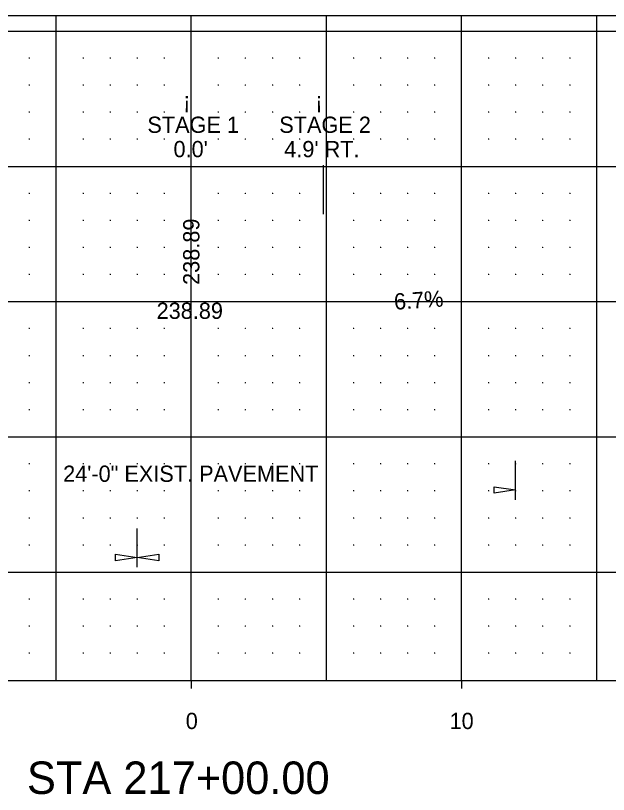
# Model space of a CAD drawing. Extents: x -80 to 80, y 222 to 253.
# Drawn here: x -6.5 to 15.43, y 221.78 to 250.57 of the extents above; entities that cross this region are included whole.
import ezdxf

# ---------------------------------------------------------------- set-up
doc = ezdxf.new("R2010")
doc.units = 0
for name, color, linetype in [('Default', 7, 'Continuous'), ('DSN_DRFT_XS Border Grid', 7, 'Continuous'), ('DSN_DRFT_XS Grid Annotations', 7, 'Continuous'), ('DSN_DRFT_XS Grid Major', 7, 'Continuous'), ('DSN_DRFT_XS Grid Minor', 7, 'Continuous'), ('DSN_DRFT_XS MOT CL Annotations', 7, 'Continuous'), ('DSN_DRFT_XS MOT STG Annotations', 7, 'Continuous'), ('DSN_RDWY_XS Annotation', 7, 'Continuous')]:
    doc.layers.add(name, color=color, linetype=linetype)

msp = doc.modelspace()

# ---------------------------------------------------------------- linework, layer by layer
at = {"layer": 'DSN_DRFT_XS Border Grid'}
for p, q in [((-77.5, 250.573), (77.5, 250.573)), ((-77.5, 226), (77.5, 226))]:
    msp.add_line(p, q, dxfattribs=at)
at = {"layer": 'DSN_DRFT_XS Grid Major'}
for p, q in [((-5, 226), (-5, 250.573)), ((0, 226), (0, 250.573)), ((5, 226), (5, 250.573)), ((10, 226), (10, 250.573)), ((15, 226), (15, 250.573)), ((-77.5, 250), (77.5, 250)), ((-77.5, 245), (77.5, 245)), ((-77.5, 240), (77.5, 240)), ((-77.5, 235), (77.5, 235)), ((-77.5, 230), (77.5, 230)), ((0, 226), (0, 225.7)), ((10, 226), (10, 225.7))]:
    msp.add_line(p, q, dxfattribs=at)
at = {"layer": 'DSN_DRFT_XS Grid Minor'}
for p, q in [((-5.988, 249), (-6.012, 249)), ((-6, 249.012), (-6, 248.988)), ((-3.988, 249), (-4.012, 249)), ((-4, 249.012), (-4, 248.988)), ((-2.988, 249), (-3.012, 249)), ((-3, 249.012), (-3, 248.988)), ((-1.988, 249), (-2.012, 249)), ((-2, 249.012), (-2, 248.988)), ((-0.988, 249), (-1.012, 249)), ((-1, 249.012), (-1, 248.988)), ((1.012, 249), (0.988, 249)), ((1, 249.012), (1, 248.988)), ((2.012, 249), (1.988, 249)), ((2, 249.012), (2, 248.988)), ((3.012, 249), (2.988, 249)), ((3, 249.012), (3, 248.988)), ((4.012, 249), (3.988, 249)), ((4, 249.012), (4, 248.988)), ((6.012, 249), (5.988, 249)), ((6, 249.012), (6, 248.988)), ((7.012, 249), (6.988, 249)), ((7, 249.012), (7, 248.988)), ((8.012, 249), (7.988, 249)), ((8, 249.012), (8, 248.988)), ((9.012, 249), (8.988, 249)), ((9, 249.012), (9, 248.988)), ((11.012, 249), (10.988, 249)), ((11, 249.012), (11, 248.988)), ((12.012, 249), (11.988, 249)), ((12, 249.012), (12, 248.988)), ((13.012, 249), (12.988, 249)), ((13, 249.012), (13, 248.988)), ((14.012, 249), (13.988, 249)), ((14, 249.012), (14, 248.988)), ((-5.988, 248), (-6.012, 248)), ((-6, 248.012), (-6, 247.988)), ((-3.988, 248), (-4.012, 248)), ((-4, 248.012), (-4, 247.988)), ((-2.988, 248), (-3.012, 248)), ((-3, 248.012), (-3, 247.988)), ((-1.988, 248), (-2.012, 248)), ((-2, 248.012), (-2, 247.988)), ((-0.988, 248), (-1.012, 248)), ((-1, 248.012), (-1, 247.988)), ((1.012, 248), (0.988, 248)), ((1, 248.012), (1, 247.988)), ((2.012, 248), (1.988, 248)), ((2, 248.012), (2, 247.988)), ((3.012, 248), (2.988, 248)), ((3, 248.012), (3, 247.988)), ((4.012, 248), (3.988, 248)), ((4, 248.012), (4, 247.988)), ((6.012, 248), (5.988, 248)), ((6, 248.012), (6, 247.988)), ((7.012, 248), (6.988, 248)), ((7, 248.012), (7, 247.988)), ((8.012, 248), (7.988, 248)), ((8, 248.012), (8, 247.988)), ((9.012, 248), (8.988, 248)), ((9, 248.012), (9, 247.988)), ((11.012, 248), (10.988, 248)), ((11, 248.012), (11, 247.988)), ((12.012, 248), (11.988, 248)), ((12, 248.012), (12, 247.988)), ((13.012, 248), (12.988, 248)), ((13, 248.012), (13, 247.988)), ((14.012, 248), (13.988, 248)), ((14, 248.012), (14, 247.988)), ((-5.988, 247), (-6.012, 247)), ((-6, 247.012), (-6, 246.988)), ((-3.988, 247), (-4.012, 247)), ((-4, 247.012), (-4, 246.988)), ((-2.988, 247), (-3.012, 247)), ((-3, 247.012), (-3, 246.988)), ((-1.988, 247), (-2.012, 247)), ((-2, 247.012), (-2, 246.988)), ((-0.988, 247), (-1.012, 247)), ((-1, 247.012), (-1, 246.988)), ((1.012, 247), (0.988, 247)), ((1, 247.012), (1, 246.988)), ((2.012, 247), (1.988, 247)), ((2, 247.012), (2, 246.988)), ((3.012, 247), (2.988, 247)), ((3, 247.012), (3, 246.988)), ((4.012, 247), (3.988, 247)), ((4, 247.012), (4, 246.988)), ((6.012, 247), (5.988, 247)), ((6, 247.012), (6, 246.988)), ((7.012, 247), (6.988, 247)), ((7, 247.012), (7, 246.988)), ((8.012, 247), (7.988, 247)), ((8, 247.012), (8, 246.988)), ((9.012, 247), (8.988, 247)), ((9, 247.012), (9, 246.988)), ((11.012, 247), (10.988, 247)), ((11, 247.012), (11, 246.988)), ((12.012, 247), (11.988, 247)), ((12, 247.012), (12, 246.988)), ((13.012, 247), (12.988, 247)), ((13, 247.012), (13, 246.988)), ((14.012, 247), (13.988, 247)), ((14, 247.012), (14, 246.988)), ((-5.988, 246), (-6.012, 246)), ((-6, 246.012), (-6, 245.988)), ((-3.988, 246), (-4.012, 246)), ((-4, 246.012), (-4, 245.988)), ((-2.988, 246), (-3.012, 246)), ((-3, 246.012), (-3, 245.988)), ((-1.988, 246), (-2.012, 246)), ((-2, 246.012), (-2, 245.988)), ((-0.988, 246), (-1.012, 246)), ((-1, 246.012), (-1, 245.988)), ((1.012, 246), (0.988, 246)), ((1, 246.012), (1, 245.988)), ((2.012, 246), (1.988, 246)), ((2, 246.012), (2, 245.988)), ((3.012, 246), (2.988, 246)), ((3, 246.012), (3, 245.988)), ((4.012, 246), (3.988, 246)), ((4, 246.012), (4, 245.988)), ((6.012, 246), (5.988, 246)), ((6, 246.012), (6, 245.988)), ((7.012, 246), (6.988, 246)), ((7, 246.012), (7, 245.988)), ((8.012, 246), (7.988, 246)), ((8, 246.012), (8, 245.988)), ((9.012, 246), (8.988, 246)), ((9, 246.012), (9, 245.988)), ((11.012, 246), (10.988, 246)), ((11, 246.012), (11, 245.988)), ((12.012, 246), (11.988, 246)), ((12, 246.012), (12, 245.988)), ((13.012, 246), (12.988, 246)), ((13, 246.012), (13, 245.988)), ((14.012, 246), (13.988, 246)), ((14, 246.012), (14, 245.988)), ((-5.988, 244), (-6.012, 244)), ((-6, 244.012), (-6, 243.988)), ((-3.988, 244), (-4.012, 244)), ((-4, 244.012), (-4, 243.988)), ((-2.988, 244), (-3.012, 244)), ((-3, 244.012), (-3, 243.988)), ((-1.988, 244), (-2.012, 244)), ((-2, 244.012), (-2, 243.988)), ((-0.988, 244), (-1.012, 244)), ((-1, 244.012), (-1, 243.988)), ((1.012, 244), (0.988, 244)), ((1, 244.012), (1, 243.988)), ((2.012, 244), (1.988, 244)), ((2, 244.012), (2, 243.988)), ((3.012, 244), (2.988, 244)), ((3, 244.012), (3, 243.988)), ((4.012, 244), (3.988, 244)), ((4, 244.012), (4, 243.988)), ((6.012, 244), (5.988, 244)), ((6, 244.012), (6, 243.988)), ((7.012, 244), (6.988, 244)), ((7, 244.012), (7, 243.988)), ((8.012, 244), (7.988, 244)), ((8, 244.012), (8, 243.988)), ((9.012, 244), (8.988, 244)), ((9, 244.012), (9, 243.988)), ((11.012, 244), (10.988, 244)), ((11, 244.012), (11, 243.988)), ((12.012, 244), (11.988, 244)), ((12, 244.012), (12, 243.988)), ((13.012, 244), (12.988, 244)), ((13, 244.012), (13, 243.988)), ((14.012, 244), (13.988, 244)), ((14, 244.012), (14, 243.988)), ((-5.988, 243), (-6.012, 243)), ((-6, 243.012), (-6, 242.988)), ((-3.988, 243), (-4.012, 243)), ((-4, 243.012), (-4, 242.988)), ((-2.988, 243), (-3.012, 243)), ((-3, 243.012), (-3, 242.988)), ((-1.988, 243), (-2.012, 243)), ((-2, 243.012), (-2, 242.988)), ((-0.988, 243), (-1.012, 243)), ((-1, 243.012), (-1, 242.988)), ((1.012, 243), (0.988, 243)), ((1, 243.012), (1, 242.988)), ((2.012, 243), (1.988, 243)), ((2, 243.012), (2, 242.988)), ((3.012, 243), (2.988, 243)), ((3, 243.012), (3, 242.988)), ((4.012, 243), (3.988, 243)), ((4, 243.012), (4, 242.988)), ((6.012, 243), (5.988, 243)), ((6, 243.012), (6, 242.988)), ((7.012, 243), (6.988, 243)), ((7, 243.012), (7, 242.988)), ((8.012, 243), (7.988, 243)), ((8, 243.012), (8, 242.988)), ((9.012, 243), (8.988, 243)), ((9, 243.012), (9, 242.988)), ((11.012, 243), (10.988, 243)), ((11, 243.012), (11, 242.988)), ((12.012, 243), (11.988, 243)), ((12, 243.012), (12, 242.988)), ((13.012, 243), (12.988, 243)), ((13, 243.012), (13, 242.988)), ((14.012, 243), (13.988, 243)), ((14, 243.012), (14, 242.988)), ((-5.988, 242), (-6.012, 242)), ((-6, 242.012), (-6, 241.988)), ((-3.988, 242), (-4.012, 242)), ((-4, 242.012), (-4, 241.988)), ((-2.988, 242), (-3.012, 242)), ((-3, 242.012), (-3, 241.988)), ((-1.988, 242), (-2.012, 242)), ((-2, 242.012), (-2, 241.988)), ((-0.988, 242), (-1.012, 242)), ((-1, 242.012), (-1, 241.988)), ((1.012, 242), (0.988, 242)), ((1, 242.012), (1, 241.988)), ((2.012, 242), (1.988, 242)), ((2, 242.012), (2, 241.988)), ((3.012, 242), (2.988, 242)), ((3, 242.012), (3, 241.988)), ((4.012, 242), (3.988, 242)), ((4, 242.012), (4, 241.988)), ((6.012, 242), (5.988, 242)), ((6, 242.012), (6, 241.988)), ((7.012, 242), (6.988, 242)), ((7, 242.012), (7, 241.988)), ((8.012, 242), (7.988, 242)), ((8, 242.012), (8, 241.988)), ((9.012, 242), (8.988, 242)), ((9, 242.012), (9, 241.988)), ((11.012, 242), (10.988, 242)), ((11, 242.012), (11, 241.988)), ((12.012, 242), (11.988, 242)), ((12, 242.012), (12, 241.988)), ((13.012, 242), (12.988, 242)), ((13, 242.012), (13, 241.988)), ((14.012, 242), (13.988, 242)), ((14, 242.012), (14, 241.988)), ((-5.988, 241), (-6.012, 241)), ((-6, 241.012), (-6, 240.988)), ((-3.988, 241), (-4.012, 241)), ((-4, 241.012), (-4, 240.988)), ((-2.988, 241), (-3.012, 241)), ((-3, 241.012), (-3, 240.988)), ((-1.988, 241), (-2.012, 241)), ((-2, 241.012), (-2, 240.988)), ((-0.988, 241), (-1.012, 241)), ((-1, 241.012), (-1, 240.988)), ((1.012, 241), (0.988, 241)), ((1, 241.012), (1, 240.988)), ((2.012, 241), (1.988, 241)), ((2, 241.012), (2, 240.988)), ((3.012, 241), (2.988, 241)), ((3, 241.012), (3, 240.988)), ((4.012, 241), (3.988, 241)), ((4, 241.012), (4, 240.988)), ((6.012, 241), (5.988, 241)), ((6, 241.012), (6, 240.988)), ((7.012, 241), (6.988, 241)), ((7, 241.012), (7, 240.988)), ((8.012, 241), (7.988, 241)), ((8, 241.012), (8, 240.988)), ((9.012, 241), (8.988, 241)), ((9, 241.012), (9, 240.988)), ((11.012, 241), (10.988, 241)), ((11, 241.012), (11, 240.988)), ((12.012, 241), (11.988, 241)), ((12, 241.012), (12, 240.988)), ((13.012, 241), (12.988, 241)), ((13, 241.012), (13, 240.988)), ((14.012, 241), (13.988, 241)), ((14, 241.012), (14, 240.988)), ((-5.988, 239), (-6.012, 239)), ((-6, 239.012), (-6, 238.988)), ((-3.988, 239), (-4.012, 239)), ((-4, 239.012), (-4, 238.988)), ((-2.988, 239), (-3.012, 239)), ((-3, 239.012), (-3, 238.988)), ((-1.988, 239), (-2.012, 239)), ((-2, 239.012), (-2, 238.988)), ((-0.988, 239), (-1.012, 239)), ((-1, 239.012), (-1, 238.988)), ((1.012, 239), (0.988, 239)), ((1, 239.012), (1, 238.988)), ((2.012, 239), (1.988, 239)), ((2, 239.012), (2, 238.988)), ((3.012, 239), (2.988, 239)), ((3, 239.012), (3, 238.988)), ((4.012, 239), (3.988, 239)), ((4, 239.012), (4, 238.988)), ((6.012, 239), (5.988, 239)), ((6, 239.012), (6, 238.988)), ((7.012, 239), (6.988, 239)), ((7, 239.012), (7, 238.988)), ((8.012, 239), (7.988, 239)), ((8, 239.012), (8, 238.988)), ((9.012, 239), (8.988, 239)), ((9, 239.012), (9, 238.988)), ((11.012, 239), (10.988, 239)), ((11, 239.012), (11, 238.988)), ((12.012, 239), (11.988, 239)), ((12, 239.012), (12, 238.988)), ((13.012, 239), (12.988, 239)), ((13, 239.012), (13, 238.988)), ((14.012, 239), (13.988, 239)), ((14, 239.012), (14, 238.988)), ((-5.988, 238), (-6.012, 238)), ((-6, 238.012), (-6, 237.988)), ((-3.988, 238), (-4.012, 238)), ((-4, 238.012), (-4, 237.988)), ((-2.988, 238), (-3.012, 238)), ((-3, 238.012), (-3, 237.988)), ((-1.988, 238), (-2.012, 238)), ((-2, 238.012), (-2, 237.988)), ((-0.988, 238), (-1.012, 238)), ((-1, 238.012), (-1, 237.988)), ((1.012, 238), (0.988, 238)), ((1, 238.012), (1, 237.988)), ((2.012, 238), (1.988, 238)), ((2, 238.012), (2, 237.988)), ((3.012, 238), (2.988, 238)), ((3, 238.012), (3, 237.988)), ((4.012, 238), (3.988, 238)), ((4, 238.012), (4, 237.988)), ((6.012, 238), (5.988, 238)), ((6, 238.012), (6, 237.988)), ((7.012, 238), (6.988, 238)), ((7, 238.012), (7, 237.988)), ((8.012, 238), (7.988, 238)), ((8, 238.012), (8, 237.988)), ((9.012, 238), (8.988, 238)), ((9, 238.012), (9, 237.988)), ((11.012, 238), (10.988, 238)), ((11, 238.012), (11, 237.988)), ((12.012, 238), (11.988, 238)), ((12, 238.012), (12, 237.988)), ((13.012, 238), (12.988, 238)), ((13, 238.012), (13, 237.988)), ((14.012, 238), (13.988, 238)), ((14, 238.012), (14, 237.988)), ((-5.988, 237), (-6.012, 237)), ((-6, 237.012), (-6, 236.988)), ((-3.988, 237), (-4.012, 237)), ((-4, 237.012), (-4, 236.988)), ((-2.988, 237), (-3.012, 237)), ((-3, 237.012), (-3, 236.988)), ((-1.988, 237), (-2.012, 237)), ((-2, 237.012), (-2, 236.988)), ((-0.988, 237), (-1.012, 237)), ((-1, 237.012), (-1, 236.988)), ((1.012, 237), (0.988, 237)), ((1, 237.012), (1, 236.988)), ((2.012, 237), (1.988, 237)), ((2, 237.012), (2, 236.988)), ((3.012, 237), (2.988, 237)), ((3, 237.012), (3, 236.988)), ((4.012, 237), (3.988, 237)), ((4, 237.012), (4, 236.988)), ((6.012, 237), (5.988, 237)), ((6, 237.012), (6, 236.988)), ((7.012, 237), (6.988, 237)), ((7, 237.012), (7, 236.988)), ((8.012, 237), (7.988, 237)), ((8, 237.012), (8, 236.988)), ((9.012, 237), (8.988, 237)), ((9, 237.012), (9, 236.988)), ((11.012, 237), (10.988, 237)), ((11, 237.012), (11, 236.988)), ((12.012, 237), (11.988, 237)), ((12, 237.012), (12, 236.988)), ((13.012, 237), (12.988, 237)), ((13, 237.012), (13, 236.988)), ((14.012, 237), (13.988, 237)), ((14, 237.012), (14, 236.988)), ((-5.988, 236), (-6.012, 236)), ((-6, 236.012), (-6, 235.988)), ((-3.988, 236), (-4.012, 236)), ((-4, 236.012), (-4, 235.988)), ((-2.988, 236), (-3.012, 236)), ((-3, 236.012), (-3, 235.988)), ((-1.988, 236), (-2.012, 236)), ((-2, 236.012), (-2, 235.988)), ((-0.988, 236), (-1.012, 236)), ((-1, 236.012), (-1, 235.988)), ((1.012, 236), (0.988, 236)), ((1, 236.012), (1, 235.988)), ((2.012, 236), (1.988, 236)), ((2, 236.012), (2, 235.988)), ((3.012, 236), (2.988, 236)), ((3, 236.012), (3, 235.988)), ((4.012, 236), (3.988, 236)), ((4, 236.012), (4, 235.988)), ((6.012, 236), (5.988, 236)), ((6, 236.012), (6, 235.988)), ((7.012, 236), (6.988, 236)), ((7, 236.012), (7, 235.988)), ((8.012, 236), (7.988, 236)), ((8, 236.012), (8, 235.988)), ((9.012, 236), (8.988, 236)), ((9, 236.012), (9, 235.988)), ((11.012, 236), (10.988, 236)), ((11, 236.012), (11, 235.988)), ((12.012, 236), (11.988, 236)), ((12, 236.012), (12, 235.988)), ((13.012, 236), (12.988, 236)), ((13, 236.012), (13, 235.988)), ((14.012, 236), (13.988, 236)), ((14, 236.012), (14, 235.988)), ((-5.988, 234), (-6.012, 234)), ((-6, 234.012), (-6, 233.988)), ((-3.988, 234), (-4.012, 234)), ((-4, 234.012), (-4, 233.988)), ((-2.988, 234), (-3.012, 234)), ((-3, 234.012), (-3, 233.988)), ((-1.988, 234), (-2.012, 234)), ((-2, 234.012), (-2, 233.988)), ((-0.988, 234), (-1.012, 234)), ((-1, 234.012), (-1, 233.988)), ((1.012, 234), (0.988, 234)), ((1, 234.012), (1, 233.988)), ((2.012, 234), (1.988, 234)), ((2, 234.012), (2, 233.988)), ((3.012, 234), (2.988, 234)), ((3, 234.012), (3, 233.988)), ((4.012, 234), (3.988, 234)), ((4, 234.012), (4, 233.988)), ((6.012, 234), (5.988, 234)), ((6, 234.012), (6, 233.988)), ((7.012, 234), (6.988, 234)), ((7, 234.012), (7, 233.988)), ((8.012, 234), (7.988, 234)), ((8, 234.012), (8, 233.988)), ((9.012, 234), (8.988, 234)), ((9, 234.012), (9, 233.988)), ((11.012, 234), (10.988, 234)), ((11, 234.012), (11, 233.988)), ((12.012, 234), (11.988, 234)), ((12, 234.012), (12, 233.988)), ((13.012, 234), (12.988, 234)), ((13, 234.012), (13, 233.988)), ((14.012, 234), (13.988, 234)), ((14, 234.012), (14, 233.988)), ((-5.988, 233), (-6.012, 233)), ((-6, 233.012), (-6, 232.988)), ((-3.988, 233), (-4.012, 233)), ((-4, 233.012), (-4, 232.988)), ((-2.988, 233), (-3.012, 233)), ((-3, 233.012), (-3, 232.988)), ((-1.988, 233), (-2.012, 233)), ((-2, 233.012), (-2, 232.988)), ((-0.988, 233), (-1.012, 233)), ((-1, 233.012), (-1, 232.988)), ((1.012, 233), (0.988, 233)), ((1, 233.012), (1, 232.988)), ((2.012, 233), (1.988, 233)), ((2, 233.012), (2, 232.988)), ((3.012, 233), (2.988, 233)), ((3, 233.012), (3, 232.988)), ((4.012, 233), (3.988, 233)), ((4, 233.012), (4, 232.988)), ((6.012, 233), (5.988, 233)), ((6, 233.012), (6, 232.988)), ((7.012, 233), (6.988, 233)), ((7, 233.012), (7, 232.988)), ((8.012, 233), (7.988, 233)), ((8, 233.012), (8, 232.988)), ((9.012, 233), (8.988, 233)), ((9, 233.012), (9, 232.988)), ((11.012, 233), (10.988, 233)), ((11, 233.012), (11, 232.988)), ((12.012, 233), (11.988, 233)), ((12, 233.012), (12, 232.988)), ((13.012, 233), (12.988, 233)), ((13, 233.012), (13, 232.988)), ((14.012, 233), (13.988, 233)), ((14, 233.012), (14, 232.988)), ((-5.988, 232), (-6.012, 232)), ((-6, 232.012), (-6, 231.988)), ((-3.988, 232), (-4.012, 232)), ((-4, 232.012), (-4, 231.988)), ((-2.988, 232), (-3.012, 232)), ((-3, 232.012), (-3, 231.988)), ((-1.988, 232), (-2.012, 232)), ((-2, 232.012), (-2, 231.988)), ((-0.988, 232), (-1.012, 232)), ((-1, 232.012), (-1, 231.988)), ((1.012, 232), (0.988, 232)), ((1, 232.012), (1, 231.988)), ((2.012, 232), (1.988, 232)), ((2, 232.012), (2, 231.988)), ((3.012, 232), (2.988, 232)), ((3, 232.012), (3, 231.988)), ((4.012, 232), (3.988, 232)), ((4, 232.012), (4, 231.988)), ((6.012, 232), (5.988, 232)), ((6, 232.012), (6, 231.988)), ((7.012, 232), (6.988, 232)), ((7, 232.012), (7, 231.988)), ((8.012, 232), (7.988, 232)), ((8, 232.012), (8, 231.988)), ((9.012, 232), (8.988, 232)), ((9, 232.012), (9, 231.988)), ((11.012, 232), (10.988, 232)), ((11, 232.012), (11, 231.988)), ((12.012, 232), (11.988, 232)), ((12, 232.012), (12, 231.988)), ((13.012, 232), (12.988, 232)), ((13, 232.012), (13, 231.988)), ((14.012, 232), (13.988, 232)), ((14, 232.012), (14, 231.988)), ((-5.988, 231), (-6.012, 231)), ((-6, 231.012), (-6, 230.988)), ((-3.988, 231), (-4.012, 231)), ((-4, 231.012), (-4, 230.988)), ((-2.988, 231), (-3.012, 231)), ((-3, 231.012), (-3, 230.988)), ((-1.988, 231), (-2.012, 231)), ((-2, 231.012), (-2, 230.988)), ((-0.988, 231), (-1.012, 231)), ((-1, 231.012), (-1, 230.988)), ((1.012, 231), (0.988, 231)), ((1, 231.012), (1, 230.988)), ((2.012, 231), (1.988, 231)), ((2, 231.012), (2, 230.988)), ((3.012, 231), (2.988, 231)), ((3, 231.012), (3, 230.988)), ((4.012, 231), (3.988, 231)), ((4, 231.012), (4, 230.988)), ((6.012, 231), (5.988, 231)), ((6, 231.012), (6, 230.988)), ((7.012, 231), (6.988, 231)), ((7, 231.012), (7, 230.988)), ((8.012, 231), (7.988, 231)), ((8, 231.012), (8, 230.988)), ((9.012, 231), (8.988, 231)), ((9, 231.012), (9, 230.988)), ((11.012, 231), (10.988, 231)), ((11, 231.012), (11, 230.988)), ((12.012, 231), (11.988, 231)), ((12, 231.012), (12, 230.988)), ((13.012, 231), (12.988, 231)), ((13, 231.012), (13, 230.988)), ((14.012, 231), (13.988, 231)), ((14, 231.012), (14, 230.988)), ((-5.988, 229), (-6.012, 229)), ((-6, 229.012), (-6, 228.988)), ((-3.988, 229), (-4.012, 229)), ((-4, 229.012), (-4, 228.988)), ((-2.988, 229), (-3.012, 229)), ((-3, 229.012), (-3, 228.988)), ((-1.988, 229), (-2.012, 229)), ((-2, 229.012), (-2, 228.988)), ((-0.988, 229), (-1.012, 229)), ((-1, 229.012), (-1, 228.988)), ((1.012, 229), (0.988, 229)), ((1, 229.012), (1, 228.988)), ((2.012, 229), (1.988, 229)), ((2, 229.012), (2, 228.988)), ((3.012, 229), (2.988, 229)), ((3, 229.012), (3, 228.988)), ((4.012, 229), (3.988, 229)), ((4, 229.012), (4, 228.988)), ((6.012, 229), (5.988, 229)), ((6, 229.012), (6, 228.988)), ((7.012, 229), (6.988, 229)), ((7, 229.012), (7, 228.988)), ((8.012, 229), (7.988, 229)), ((8, 229.012), (8, 228.988)), ((9.012, 229), (8.988, 229)), ((9, 229.012), (9, 228.988)), ((11.012, 229), (10.988, 229)), ((11, 229.012), (11, 228.988)), ((12.012, 229), (11.988, 229)), ((12, 229.012), (12, 228.988)), ((13.012, 229), (12.988, 229)), ((13, 229.012), (13, 228.988)), ((14.012, 229), (13.988, 229)), ((14, 229.012), (14, 228.988)), ((-5.988, 228), (-6.012, 228)), ((-6, 228.012), (-6, 227.988)), ((-3.988, 228), (-4.012, 228)), ((-4, 228.012), (-4, 227.988)), ((-2.988, 228), (-3.012, 228)), ((-3, 228.012), (-3, 227.988)), ((-1.988, 228), (-2.012, 228)), ((-2, 228.012), (-2, 227.988)), ((-0.988, 228), (-1.012, 228)), ((-1, 228.012), (-1, 227.988)), ((1.012, 228), (0.988, 228)), ((1, 228.012), (1, 227.988)), ((2.012, 228), (1.988, 228)), ((2, 228.012), (2, 227.988)), ((3.012, 228), (2.988, 228)), ((3, 228.012), (3, 227.988)), ((4.012, 228), (3.988, 228)), ((4, 228.012), (4, 227.988)), ((6.012, 228), (5.988, 228)), ((6, 228.012), (6, 227.988)), ((7.012, 228), (6.988, 228)), ((7, 228.012), (7, 227.988)), ((8.012, 228), (7.988, 228)), ((8, 228.012), (8, 227.988)), ((9.012, 228), (8.988, 228)), ((9, 228.012), (9, 227.988)), ((11.012, 228), (10.988, 228)), ((11, 228.012), (11, 227.988)), ((12.012, 228), (11.988, 228)), ((12, 228.012), (12, 227.988)), ((13.012, 228), (12.988, 228)), ((13, 228.012), (13, 227.988)), ((14.012, 228), (13.988, 228)), ((14, 228.012), (14, 227.988)), ((-5.988, 227), (-6.012, 227)), ((-6, 227.012), (-6, 226.988)), ((-3.988, 227), (-4.012, 227)), ((-4, 227.012), (-4, 226.988)), ((-2.988, 227), (-3.012, 227)), ((-3, 227.012), (-3, 226.988)), ((-1.988, 227), (-2.012, 227)), ((-2, 227.012), (-2, 226.988)), ((-0.988, 227), (-1.012, 227)), ((-1, 227.012), (-1, 226.988)), ((1.012, 227), (0.988, 227)), ((1, 227.012), (1, 226.988)), ((2.012, 227), (1.988, 227)), ((2, 227.012), (2, 226.988)), ((3.012, 227), (2.988, 227)), ((3, 227.012), (3, 226.988)), ((4.012, 227), (3.988, 227)), ((4, 227.012), (4, 226.988)), ((6.012, 227), (5.988, 227)), ((6, 227.012), (6, 226.988)), ((7.012, 227), (6.988, 227)), ((7, 227.012), (7, 226.988)), ((8.012, 227), (7.988, 227)), ((8, 227.012), (8, 226.988)), ((9.012, 227), (8.988, 227)), ((9, 227.012), (9, 226.988)), ((11.012, 227), (10.988, 227)), ((11, 227.012), (11, 226.988)), ((12.012, 227), (11.988, 227)), ((12, 227.012), (12, 226.988)), ((13.012, 227), (12.988, 227)), ((13, 227.012), (13, 226.988)), ((14.012, 227), (13.988, 227)), ((14, 227.012), (14, 226.988))]:
    msp.add_line(p, q, dxfattribs=at)
at = {"layer": 'DSN_DRFT_XS MOT CL Annotations'}
for p, q in [((0, 243.238), (0, 245.038)), ((4.889, 243.238), (4.889, 245.038))]:
    msp.add_line(p, q, dxfattribs=at)
at = {"layer": 'DSN_DRFT_XS MOT STG Annotations'}
for p, q in [((12, 232.678), (12, 234.118)), ((-2, 230.178), (-2, 231.618)), ((-2, 230.178), (-2, 231.618))]:
    msp.add_line(p, q, dxfattribs=at)
for points in [[(11.2, 233.158), (12, 233.038), (11.2, 232.918)], [(-2.8, 230.658), (-2, 230.538), (-2.8, 230.418)], [(-1.2, 230.418), (-2, 230.538), (-1.2, 230.658)]]:
    msp.add_lwpolyline(points, close=True, dxfattribs=at)

# ---------------------------------------------------------------- texts
at = {"layer": 'Default'}
for s, p in [("0.0'", (-0.657, 245.338)), ("4.9' RT.", (3.441, 245.338)), ('24\'-0" EXIST. PAVEMENT', (-4.741, 233.338))]:
    msp.add_text(s, height=0.6, dxfattribs=at).set_placement(p)
at = {"layer": 'DSN_DRFT_XS Grid Annotations'}
for s, height, p in [('0', 0.6, (-0.205, 224.2)), ('10', 0.6, (9.555, 224.2)), ('STA 217+00.00', 1.2, (-6.078, 221.8))]:
    msp.add_text(s, height=height, dxfattribs=at).set_placement(p)
at = {"layer": 'DSN_DRFT_XS MOT CL Annotations'}
for s, p in [('¡', (-0.299, 247.138)), ('¡', (4.59, 247.138)), ('STAGE 1', (-1.623, 246.238)), ('STAGE 2', (3.256, 246.238))]:
    msp.add_text(s, height=0.6, dxfattribs=at).set_placement(p)
at = {"layer": 'DSN_RDWY_XS Annotation'}
for s, rotation, p in [('238.89', 90, (0.3, 240.617)), ('6.7%', 3.8537, (7.52, 239.697)), ('6.7%', 3.8537, (7.52, 239.697))]:
    msp.add_text(s, height=0.6, rotation=rotation, dxfattribs=at).set_placement(p)
msp.add_text('238.89', height=0.6, dxfattribs=at).set_placement((-1.282, 239.362))

doc.saveas('drawing.dxf')
